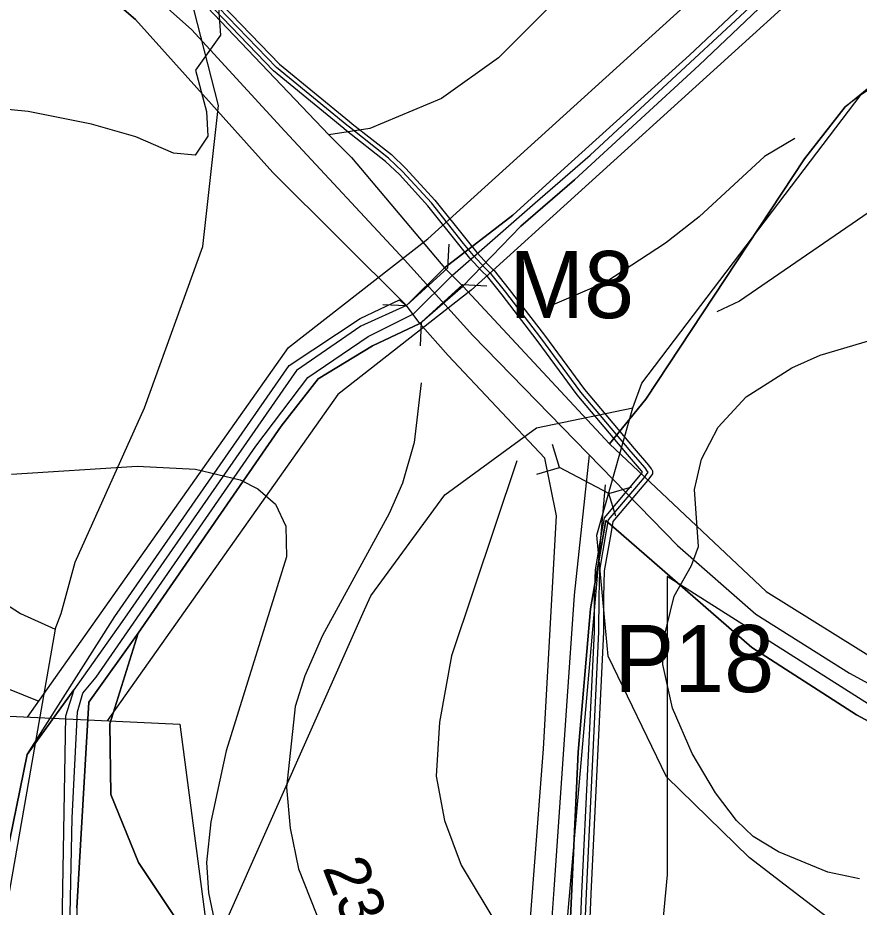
# Model space of a CAD drawing. Extents: x -662500 to -655523, y -1056000 to -1049993.
# Drawn here: x -660171.3 to -659983.5, y -1053065.6 to -1052866.9 of the extents above; entities that cross this region are included whole.
import ezdxf

# ---------------------------------------------------------------- set-up
doc = ezdxf.new("R2010")
doc.units = 0
for name, color, linetype in [('63LINIE', 7, 'Continuous'), ('Vrstva 11', 7, 'Continuous'), ('Vrstva 17', 7, 'Continuous'), ('Vrstva 24', 7, 'Continuous'), ('Vrstva 32', 7, 'Continuous'), ('Vrstva 37', 7, 'Continuous'), ('Vrstva 42', 7, 'Continuous'), ('Vrstva 47', 7, 'Continuous'), ('Vrstva 5', 7, 'Continuous'), ('Vrstva 50', 7, 'Continuous'), ('Vrstva 51', 7, 'Continuous'), ('Vrstva 57', 7, 'Continuous'), ('Vrstva 6', 7, 'Continuous'), ('Vrstva 61', 7, 'Continuous'), ('Vrstva 7', 7, 'Continuous')]:
    doc.layers.add(name, color=color, linetype=linetype)

# ---------------------------------------------------------------- blocks, each defined once
blk = doc.blocks.new('PSZ021')
at = {"layer": 'Vrstva 17'}
for points in [[(-10.01, 6.26), (-6.26, 2.51), (6.24, 2.51), (9.99, 6.26)], [(-10.01, -6.24), (-6.26, -2.49), (6.24, -2.49), (9.99, -6.24)]]:
    blk.add_lwpolyline(points, dxfattribs=at)

msp = doc.modelspace()

# ---------------------------------------------------------------- linework, layer by layer
at = {"layer": '63LINIE'}
msp.add_lwpolyline([(-660157.65, -1052847.13), (-660132.52, -1052869.51), (-660111.66, -1052892.24), (-660084.95, -1052921), (-660069.74, -1052937.89), (-660023.99, -1052984.81), (-660006.51, -1053000.13), (-659985.6, -1053013.28), (-659850.42, -1053086.91), (-659781.9, -1053123.24), (-659710.72, -1053161.03), (-659675.58, -1053176.35), (-659546.48, -1053229.26), (-659428.67, -1053277.07), (-659332.46, -1053315.26), (-659288.19, -1053334.01)], dxfattribs=at)
at = {"layer": 'Vrstva 11'}
msp.add_lwpolyline([(-660043.77, -1052964.52), (-660047.11, -1052995.9), (-660048.8, -1053020.58), (-660051.61, -1053061.61), (-660052.93, -1053079.39), (-660057.59, -1053114.8), (-660060.88, -1053162.14), (-660061.5, -1053172.08), (-660065.23, -1053196.24), (-660068.52, -1053209.73), (-660080.33, -1053244.37), (-660088.5, -1053263.64), (-660096.4, -1053281.22), (-660102.08, -1053296.45), (-660104.3, -1053303.24), (-660111.19, -1053332.15), (-660115.89, -1053363.94), (-660119.67, -1053410.57), (-660121.55, -1053443.11), (-660128.59, -1053535.41), (-660141.02, -1053666.13)], dxfattribs=at)
at = {"layer": 'Vrstva 24'}
for points in [[(-660034, -1052954), (-660032, -1052948.5), (-660000, -1052906.38), (-659983, -1052884), (-659923.5, -1052843.5), (-659891.5, -1052807.5), (-659876.5, -1052780.5), (-659868, -1052749), (-659871, -1052717.5), (-659880, -1052690.5), (-659893, -1052641), (-659893, -1052609.5), (-659864.5, -1052533), (-659861.5, -1052506), (-659866.5, -1052474.5), (-659880.5, -1052438.5), (-659901.5, -1052398), (-659927, -1052348.5), (-659940, -1052302)], [(-660163, -1053003.5), (-660161.64, -1053000), (-660158.5, -1052988.5), (-660143, -1052954), (-660130, -1052918), (-660126.5, -1052886.5), (-660132, -1052865)], [(-660331, -1053241.5), (-660301, -1053212), (-660278, -1053198), (-660227.5, -1053179), (-660190.5, -1053163), (-660174, -1053153.5), (-660166, -1053148.5), (-660158, -1053138.5), (-660146, -1053116.5), (-660094.29, -1053000), (-660092.5, -1052996), (-660076, -1052973.5), (-660055.5, -1052958.5), (-660034, -1052954)], [(-659728.49, -1053235.51), (-659755.5, -1053223.5), (-659901.5, -1053140), (-659970.5, -1053087.5), (-659990.5, -1053068), (-660000, -1053060.67), (-660008, -1053054.5), (-660026.5, -1053036.5), (-660039.5, -1053009.5), (-660040.38, -1053000), (-660042, -1052982.5), (-660034, -1052954)], [(-660322, -1052973), (-660298, -1052967.5), (-660263, -1052966), (-660228, -1052971.5), (-660198.5, -1052982), (-660170.72, -1053000), (-660163, -1053003.5)], [(-660163, -1053003.5), (-660174, -1053066.5), (-660178.5, -1053074), (-660183, -1053084.5), (-660192.5, -1053091.5), (-660213.5, -1053095), (-660260.5, -1053096.5), (-660299, -1053106), (-660322, -1053122.5), (-660356.5, -1053167.5), (-660401, -1053208), (-660418.5, -1053226), (-660434.5, -1053237.5)]]:
    msp.add_lwpolyline(points, dxfattribs=at)
at = {"layer": 'Vrstva 32'}
msp.add_lwpolyline([(-660160.88, -1053125.12), (-660160.66, -1053117.41), (-660159.16, -1053045.6), (-660157.94, -1053021.94), (-660156.76, -1053017.77), (-660153.81, -1053014.23), (-660118.13, -1052962.6), (-660106.54, -1052947.23), (-660093.09, -1052938.1), (-660082.98, -1052933), (-660074.25, -1052924.36), (-660055.79, -1052908.21), (-660043.52, -1052897.56), (-659991.83, -1052849.55)], dxfattribs=at)
at = {"layer": 'Vrstva 37'}
msp.add_lwpolyline([(-660026.32, -1052991.73), (-660026.32, -1053058.37), (-660035.43, -1053154.64), (-660050.23, -1053231.54), (-659773.69, -1053361.27), (-659704.27, -1053171.81), (-659884.58, -1053081.65)], close=True, dxfattribs=at)
at = {"layer": 'Vrstva 42'}
for p, q in [((-660065.77, -1052923.99), (-660066.99, -1052922.81)), ((-660065.71, -1052924.04), (-660065.77, -1052923.99)), ((-660039.42, -1052979.02), (-660031.5, -1052969.65)), ((-660039.93, -1052981.98), (-660039.42, -1052979.02))]:
    msp.add_line(p, q, dxfattribs=at)
for points in [[(-660071.79, -1052917.29), (-660078.98, -1052908.26), (-660085.4, -1052901.23), (-660088.54, -1052898.23), (-660097.28, -1052891.36), (-660097.88, -1052890.86), (-660113.54, -1052878.01), (-660128.62, -1052862.3), (-660142.63, -1052848.21), (-660154.25, -1052838.33), (-660171.42, -1052826.63), (-660193.06, -1052813.87), (-660215.92, -1052802.12), (-660236.98, -1052791.1), (-660257.23, -1052778.77), (-660267.65, -1052767.16), (-660272.2, -1052758.2)], [(-660066.99, -1052922.81), (-660069.6, -1052919.97), (-660071.79, -1052917.29)], [(-660030.72, -1052968.24), (-660031.28, -1052967.46), (-660034.46, -1052963.79), (-660045.6, -1052950.52), (-660054.52, -1052938.4), (-660062.35, -1052928.19), (-660065.71, -1052924.04)], [(-660031.5, -1052969.65), (-660030.58, -1052968.43), (-660030.72, -1052968.24)], [(-660088.15, -1053276.4), (-660075.09, -1053253.54), (-660063.07, -1053219.83), (-660055.85, -1053184.99), (-660053.25, -1053160.83), (-660052.11, -1053157.3), (-660050.97, -1053154.4), (-660049.97, -1053151.48), (-660047.52, -1053138.32), (-660046.36, -1053113.18), (-660046.14, -1053108.29), (-660045.22, -1053082.55), (-660044.35, -1053062.53), (-660041.58, -1053004.07), (-660041.53, -1052996.23), (-660041.37, -1052990.33), (-660039.93, -1052981.98)]]:
    msp.add_lwpolyline(points, dxfattribs=at)
at = {"layer": 'Vrstva 47'}
for points in [[(-660127.9, -1052861.6), (-660112.86, -1052877.28), (-660097.24, -1052890.09), (-660096.65, -1052890.58), (-660087.89, -1052897.47), (-660084.68, -1052900.53), (-660078.21, -1052907.61), (-660071.02, -1052916.67), (-660068.85, -1052919.31), (-660066.27, -1052922.11), (-660065.07, -1052923.27), (-660064.97, -1052923.36), (-660061.57, -1052927.57), (-660053.72, -1052937.8), (-660044.82, -1052949.9), (-660033.7, -1052963.15), (-660030.5, -1052966.84), (-660029.91, -1052967.65), (-660029.77, -1052967.84), (-660029.58, -1052968.1), (-660029.58, -1052968.76), (-660029.78, -1052969.03), (-660030.72, -1052970.28), (-660038.48, -1052979.46), (-660038.94, -1052982.15), (-660040.37, -1052990.43), (-660040.53, -1052996.24), (-660040.58, -1053004.1), (-660043.35, -1053062.58), (-660044.22, -1053082.59)], [(-660046.22, -1053082.51), (-660045.35, -1053062.49), (-660042.58, -1053004.04), (-660042.53, -1052996.21), (-660042.37, -1052990.23), (-660040.91, -1052981.8), (-660040.35, -1052978.59), (-660032.28, -1052969.03), (-660031.82, -1052968.42), (-660032.06, -1052968.08), (-660035.22, -1052964.44), (-660046.39, -1052951.13), (-660055.32, -1052939), (-660063.14, -1052928.8), (-660066.45, -1052924.72), (-660066.46, -1052924.71), (-660067.7, -1052923.51), (-660070.36, -1052920.63), (-660072.57, -1052917.92), (-660079.74, -1052908.91), (-660086.11, -1052901.93), (-660089.2, -1052898.99), (-660097.91, -1052892.14), (-660098.51, -1052891.64), (-660114.22, -1052878.75), (-660129.33, -1052863)]]:
    msp.add_lwpolyline(points, dxfattribs=at)
at = {"layer": 'Vrstva 5'}
for points in [[(-659983.56, -1052839.55), (-660021.37, -1052875.26), (-660049.28, -1052900.52), (-660060.79, -1052911.01), (-660076.02, -1052922.76), (-660084.53, -1052931.2), (-660094.75, -1052935.76), (-660109.05, -1052945.68), (-660148.01, -1053001.78), (-660158.78, -1053017), (-660160.63, -1053022.92), (-660161.37, -1053065.69)], [(-660031.73, -1052843.45), (-660064, -1052875.84), (-660076.7, -1052884.94), (-660092.72, -1052891.64), (-660101.87, -1052893.05), (-660096.81, -1052898.11), (-660076.02, -1052922.76), (-660060.79, -1052911.01), (-660049.28, -1052900.52), (-660021.37, -1052875.26), (-659983.56, -1052839.55)], [(-660158.13, -1053065.76), (-660155.45, -1053019.8), (-660144.4, -1053004.38), (-660112.49, -1052958.14), (-660104.22, -1052947.56), (-660092.12, -1052940.17), (-660081.53, -1052935.22), (-660071.92, -1052926.88), (-660059.01, -1052913.47), (-660047.02, -1052903.13), (-660019.16, -1052877.46), (-659980.71, -1052840.86)], [(-659980.71, -1052840.86), (-660019.16, -1052877.46), (-660047.02, -1052903.13), (-660059.01, -1052913.47), (-660071.92, -1052926.88), (-660039.24, -1052962.1), (-660031.07, -1052952.12), (-659995.64, -1052898.4), (-659986.59, -1052886.79), (-659977.95, -1052879.73), (-659969.58, -1052873.81), (-659937.32, -1052850.73)], [(-660031.73, -1052843.45), (-660064, -1052875.84), (-660076.7, -1052884.94), (-660092.72, -1052891.64), (-660101.87, -1052893.05), (-660138.02, -1052855.02)], [(-660170.48, -1052845.46), (-660145.01, -1052867.3), (-660114.36, -1052901.46), (-660084.53, -1052931.2), (-660094.75, -1052935.76), (-660109.05, -1052945.68), (-660148.01, -1053001.78), (-660158.78, -1053017), (-660169.18, -1053031.47), (-660175.58, -1053062.54)], [(-660068.36, -1053195.06), (-660065.03, -1053172.38), (-660064.33, -1053133.08), (-660064.14, -1053121.91), (-660060.42, -1053103.31), (-660057.71, -1053079.73), (-660053.97, -1053030.21), (-660051.01, -1052978.13), (-660053.61, -1052965.27), (-660075.23, -1052942.33), (-660081.53, -1052935.22), (-660084.53, -1052931.2), (-660114.36, -1052901.46), (-660145.01, -1052867.3), (-660170.48, -1052845.46)], [(-659937.32, -1052850.73), (-659969.58, -1052873.81), (-659986.59, -1052886.79), (-659995.64, -1052898.4), (-660031.07, -1052952.12), (-660039.24, -1052962.1), (-660004.2, -1052995.1), (-659978.55, -1053011.07), (-659877.72, -1053065.47), (-659795.26, -1053109.44), (-659710.99, -1053154.41), (-659678.33, -1053170.13), (-659552.14, -1053220.98), (-659353.83, -1053300.67), (-659328.92, -1053309.76), (-659307.52, -1053281.7), (-659380.3, -1053101.02), (-659414.22, -1052998.59), (-659429.64, -1052959.69), (-659439.55, -1052923.56), (-659442.36, -1052874.55), (-659444.11, -1052845.81)], [(-660138.02, -1052855.02), (-660101.87, -1052893.05), (-660096.81, -1052898.11), (-660076.02, -1052922.76), (-660071.92, -1052926.88), (-660039.24, -1052962.1), (-660004.2, -1052995.1), (-659978.55, -1053011.07), (-659877.72, -1053065.47), (-659795.26, -1053109.44)], [(-660057.3, -1053173.33), (-660052.73, -1053144.83), (-660051.02, -1053123.63), (-660048.41, -1053079.23), (-660046.22, -1053030.94), (-660043.45, -1052998.9), (-660040.02, -1052979.17), (-660007.4, -1053007.56), (-659984.03, -1053022.62), (-659883.53, -1053077.01), (-659802.22, -1053120.51), (-659716.54, -1053165.89)], [(-659716.54, -1053165.89), (-659802.22, -1053120.51), (-659883.53, -1053077.01), (-659984.03, -1053022.62), (-660007.4, -1053007.56), (-660040.02, -1052979.17), (-660043.45, -1052998.9), (-660046.22, -1053030.94), (-660048.41, -1053079.23), (-660051.02, -1053123.63), (-660052.73, -1053144.83), (-660057.3, -1053173.33)]]:
    msp.add_lwpolyline(points, dxfattribs=at)
for points in [[(-660081.53, -1052935.22), (-660092.12, -1052940.17), (-660104.22, -1052947.56), (-660112.49, -1052958.14), (-660144.4, -1053004.38), (-660150.73, -1053024.65), (-660150.51, -1053040.43), (-660144.36, -1053055.57), (-660133.37, -1053072.12), (-660130.34, -1053089.39), (-660124.45, -1053106.32), (-660085.27, -1053118.51), (-660064.14, -1053121.91), (-660060.42, -1053103.31), (-660057.71, -1053079.73), (-660053.97, -1053030.21), (-660051.01, -1052978.13), (-660053.61, -1052965.27), (-660075.23, -1052942.33)], [(-660144.4, -1053004.38), (-660155.45, -1053019.8), (-660158.13, -1053065.76), (-660159.28, -1053125.93), (-660158.67, -1053133.25), (-660133.92, -1053118.5), (-660134.88, -1053146.27), (-660130.49, -1053145.54), (-660111.34, -1053139.03), (-660077.5, -1053133.38), (-660064.33, -1053133.08), (-660064.14, -1053121.91), (-660085.27, -1053118.51), (-660124.45, -1053106.32), (-660130.34, -1053089.39), (-660133.37, -1053072.12), (-660144.36, -1053055.57), (-660150.51, -1053040.43), (-660150.73, -1053024.65)], [(-660158.78, -1053017), (-660160.63, -1053022.92), (-660161.37, -1053065.69), (-660162.29, -1053124.36), (-660173.45, -1053120.87), (-660175.03, -1053103.15), (-660176.15, -1053079.57), (-660175.58, -1053062.54), (-660169.18, -1053031.47)]]:
    msp.add_lwpolyline(points, close=True, dxfattribs=at)
at = {"layer": 'Vrstva 50'}
msp.add_lwpolyline([(-660435.07, -1052998.4), (-660338.47, -1052921.22), (-660327.47, -1053057.73), (-660321.24, -1053097.21), (-660175.03, -1053103.15), (-660174.83, -1053022.87), (-660135.14, -1053024.72), (-660124.45, -1053106.32), (-660064.14, -1053121.91), (-660064.92, -1053137.67), (-660124.48, -1053141.31), (-660143.9, -1053158.22), (-660224.98, -1053182.72), (-660282.65, -1053206.04), (-660302.63, -1053225.87), (-660408.17, -1053286.14), (-660457.22, -1053301.47), (-660422.63, -1053240.33), (-660404.5, -1053207.93), (-660439.36, -1053118.83)], close=True, dxfattribs=at)
at = {"layer": 'Vrstva 51'}
for points in [[(-660169.13, -1053023.13), (-660110.85, -1052940.58), (-660079.74, -1052916.29), (-659950.2, -1052798.66), (-659898.58, -1052720.65), (-659915.89, -1052669.98), (-659910.89, -1052596.38), (-659900.42, -1052552.71), (-659942.19, -1052387.83), (-659921.6, -1052399.48), (-659893.5, -1052409.43), (-659785.78, -1052462.16), (-659600.37, -1052554.27), (-659621.1, -1052589.25), (-659403.17, -1052709.23)], [(-659408.68, -1052722.85), (-659645.22, -1052595.6), (-659623.64, -1052558.85), (-659899.32, -1052423.28), (-659921, -1052417.16), (-659884.97, -1052552.61), (-659896.01, -1052598.65), (-659902.05, -1052660.61), (-659882, -1052722.78), (-659938.73, -1052808.5), (-660070.07, -1052927.77), (-660099.87, -1052951.04), (-660151.35, -1053023.96)]]:
    msp.add_lwpolyline(points, dxfattribs=at)
at = {"layer": 'Vrstva 57'}
msp.add_lwpolyline([(-660289.6, -1052768.03), (-660283.97, -1052827.25), (-660271.76, -1052869.38), (-660260.42, -1052899.71), (-660230.86, -1052987.03), (-660197.02, -1053007.24), (-660166.62, -1053019.58)], dxfattribs=at)
at = {"layer": 'Vrstva 6'}
msp.add_lwpolyline([(-660169.18, -1053031.47), (-660149.65, -1053000.64), (-660110.69, -1052944.54), (-660094.85, -1052934.08), (-660086.09, -1052929.89), (-660084.53, -1052931.2), (-660094.75, -1052935.76), (-660109.05, -1052945.68), (-660148.01, -1053001.78), (-660158.78, -1053017)], close=True, dxfattribs=at)
at = {"layer": 'Vrstva 61'}
for points in [[(-660055.43, -1052968.88), (-660050.35, -1052967.33), (-660051.9, -1052962.25)], [(-660039.32, -1052973.2), (-660050.35, -1052967.33)], [(-660040.21, -1052971.27), (-660052.48, -1053111.57), (-660057.25, -1053166.08), (-660064.24, -1053210.94), (-660077.54, -1053248.19), (-660090.91, -1053279.88), (-660093.08, -1053291.6)], [(-660037.77, -1052978.27), (-660039.32, -1052973.2), (-660034.25, -1052971.65)]]:
    msp.add_lwpolyline(points, dxfattribs=at)
at = {"layer": 'Vrstva 7'}
for p, q in [((-660126.5, -1052864.56), (-660126.07, -1052870.8)), ((-660126.07, -1052870.8), (-660131.6, -1052878.59)), ((-660131.6, -1052878.59), (-660129.19, -1052887.81)), ((-660169.01, -1052887.81), (-660184.6, -1052886.25)), ((-660154.84, -1052890.64), (-660169.01, -1052887.81)), ((-660129.19, -1052887.81), (-660128.91, -1052893.33)), ((-660144.92, -1052893.48), (-660154.84, -1052890.64)), ((-660136.56, -1052897.16), (-660144.92, -1052893.48)), ((-660128.91, -1052893.33), (-660131.74, -1052897.58)), ((-659997.83, -1052893.83), (-660004.62, -1052897.87)), ((-660131.74, -1052897.58), (-660136.56, -1052897.16)), ((-660004.62, -1052897.87), (-660019.22, -1052911.33)), ((-659962.39, -1052897.3), (-660010.15, -1052930.18)), ((-660019.22, -1052911.33), (-660026.73, -1052917.28)), ((-660026.73, -1052917.28), (-660040.05, -1052925.93)), ((-660040.05, -1052925.93), (-660053.08, -1052931.52)), ((-660010.15, -1052930.18), (-660015.25, -1052932.59)), ((-659992.15, -1052942.23), (-659951.9, -1052930.32)), ((-659998.53, -1052945.06), (-659992.15, -1052942.23)), ((-660008.73, -1052951.58), (-659998.53, -1052945.06)), ((-660081.29, -1052948.44), (-660082.85, -1052961.78)), ((-660014.97, -1052958.38), (-660008.73, -1052951.58)), ((-660018.65, -1052965.47), (-660014.97, -1052958.38)), ((-660082.85, -1052961.78), (-660085.4, -1052970.85)), ((-660020.21, -1052972.27), (-660018.65, -1052965.47)), ((-660172.7, -1052968.87), (-660144.64, -1052967.03)), ((-660144.64, -1052967.03), (-660131.6, -1052967.74)), ((-660059.89, -1052965.89), (-660074.49, -1053009.4)), ((-660131.6, -1052967.74), (-660121.68, -1052970.14)), ((-660121.68, -1052970.14), (-660117.71, -1052972.13)), ((-660085.4, -1052970.85), (-660088.38, -1052977.66)), ((-660117.71, -1052972.13), (-660113.74, -1052975.53)), ((-660019.36, -1052985.02), (-660020.21, -1052972.27)), ((-660113.74, -1052975.53), (-660111.47, -1052980.49)), ((-660088.38, -1052977.66), (-660103.26, -1053004.86)), ((-660111.47, -1052980.49), (-660111.33, -1052987.29)), ((-660020.92, -1052989.28), (-660019.36, -1052985.02)), ((-660111.33, -1052987.29), (-660124.8, -1053030.66)), ((-660024.74, -1052996.08), (-660020.92, -1052989.28)), ((-660027.15, -1053005.86), (-660024.74, -1052996.08)), ((-660103.26, -1053004.86), (-660107.22, -1053013.93)), ((-660027.3, -1053011.38), (-660027.15, -1053005.86)), ((-660074.49, -1053009.4), (-660077.18, -1053024.28)), ((-660025.17, -1053021.16), (-660027.3, -1053011.38)), ((-660107.22, -1053013.93), (-660109.35, -1053020.74)), ((-660109.35, -1053020.74), (-660111.33, -1053038.88)), ((-660020.78, -1053031.22), (-660025.17, -1053021.16)), ((-660077.18, -1053024.28), (-660077.89, -1053036.33)), ((-660124.8, -1053030.66), (-660128.2, -1053046.53)), ((-660015.53, -1053040.01), (-660020.78, -1053031.22)), ((-660077.89, -1053036.33), (-660076.05, -1053046.25)), ((-660111.33, -1053038.88), (-660110.48, -1053047.95)), ((-660010.86, -1053046.25), (-660015.53, -1053040.01)), ((-660128.2, -1053046.53), (-660129.19, -1053055.6)), ((-660076.05, -1053046.25), (-660072.36, -1053056.17)), ((-660007.17, -1053049.79), (-660010.86, -1053046.25)), ((-660110.48, -1053047.95), (-660108.64, -1053057.02)), ((-660001.5, -1053053.19), (-660007.17, -1053049.79)), ((-659990.45, -1053057.73), (-660001.5, -1053053.19)), ((-660129.19, -1053055.6), (-660128.76, -1053062.4)), ((-660108.64, -1053057.02), (-660103.26, -1053070.62)), ((-660072.36, -1053056.17), (-660056.77, -1053081.96)), ((-659983.36, -1053059.28), (-659990.45, -1053057.73)), ((-660128.76, -1053062.4), (-660126.35, -1053073.74))]:
    msp.add_line(p, q, dxfattribs=at)

# ---------------------------------------------------------------- block references
at = {"layer": 'Vrstva 17', "rotation": 42.265730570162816}
msp.add_blockref('PSZ021', (-660078.21, -1052928.84), dxfattribs=at)

# ---------------------------------------------------------------- texts
at = {"layer": 'Vrstva 17'}
msp.add_text('M8', height=15, rotation=360, dxfattribs=at).set_placement((-660061.59, -1052933.99))
at = {"layer": 'Vrstva 61'}
msp.add_text('P18', height=15, dxfattribs=at).set_placement((-660038.14, -1053017.55))
at = {"layer": 'Vrstva 7'}
msp.add_text('234', height=10, rotation=291.5942, dxfattribs=at).set_placement((-660103.36, -1053056.77))

doc.saveas('drawing.dxf')
